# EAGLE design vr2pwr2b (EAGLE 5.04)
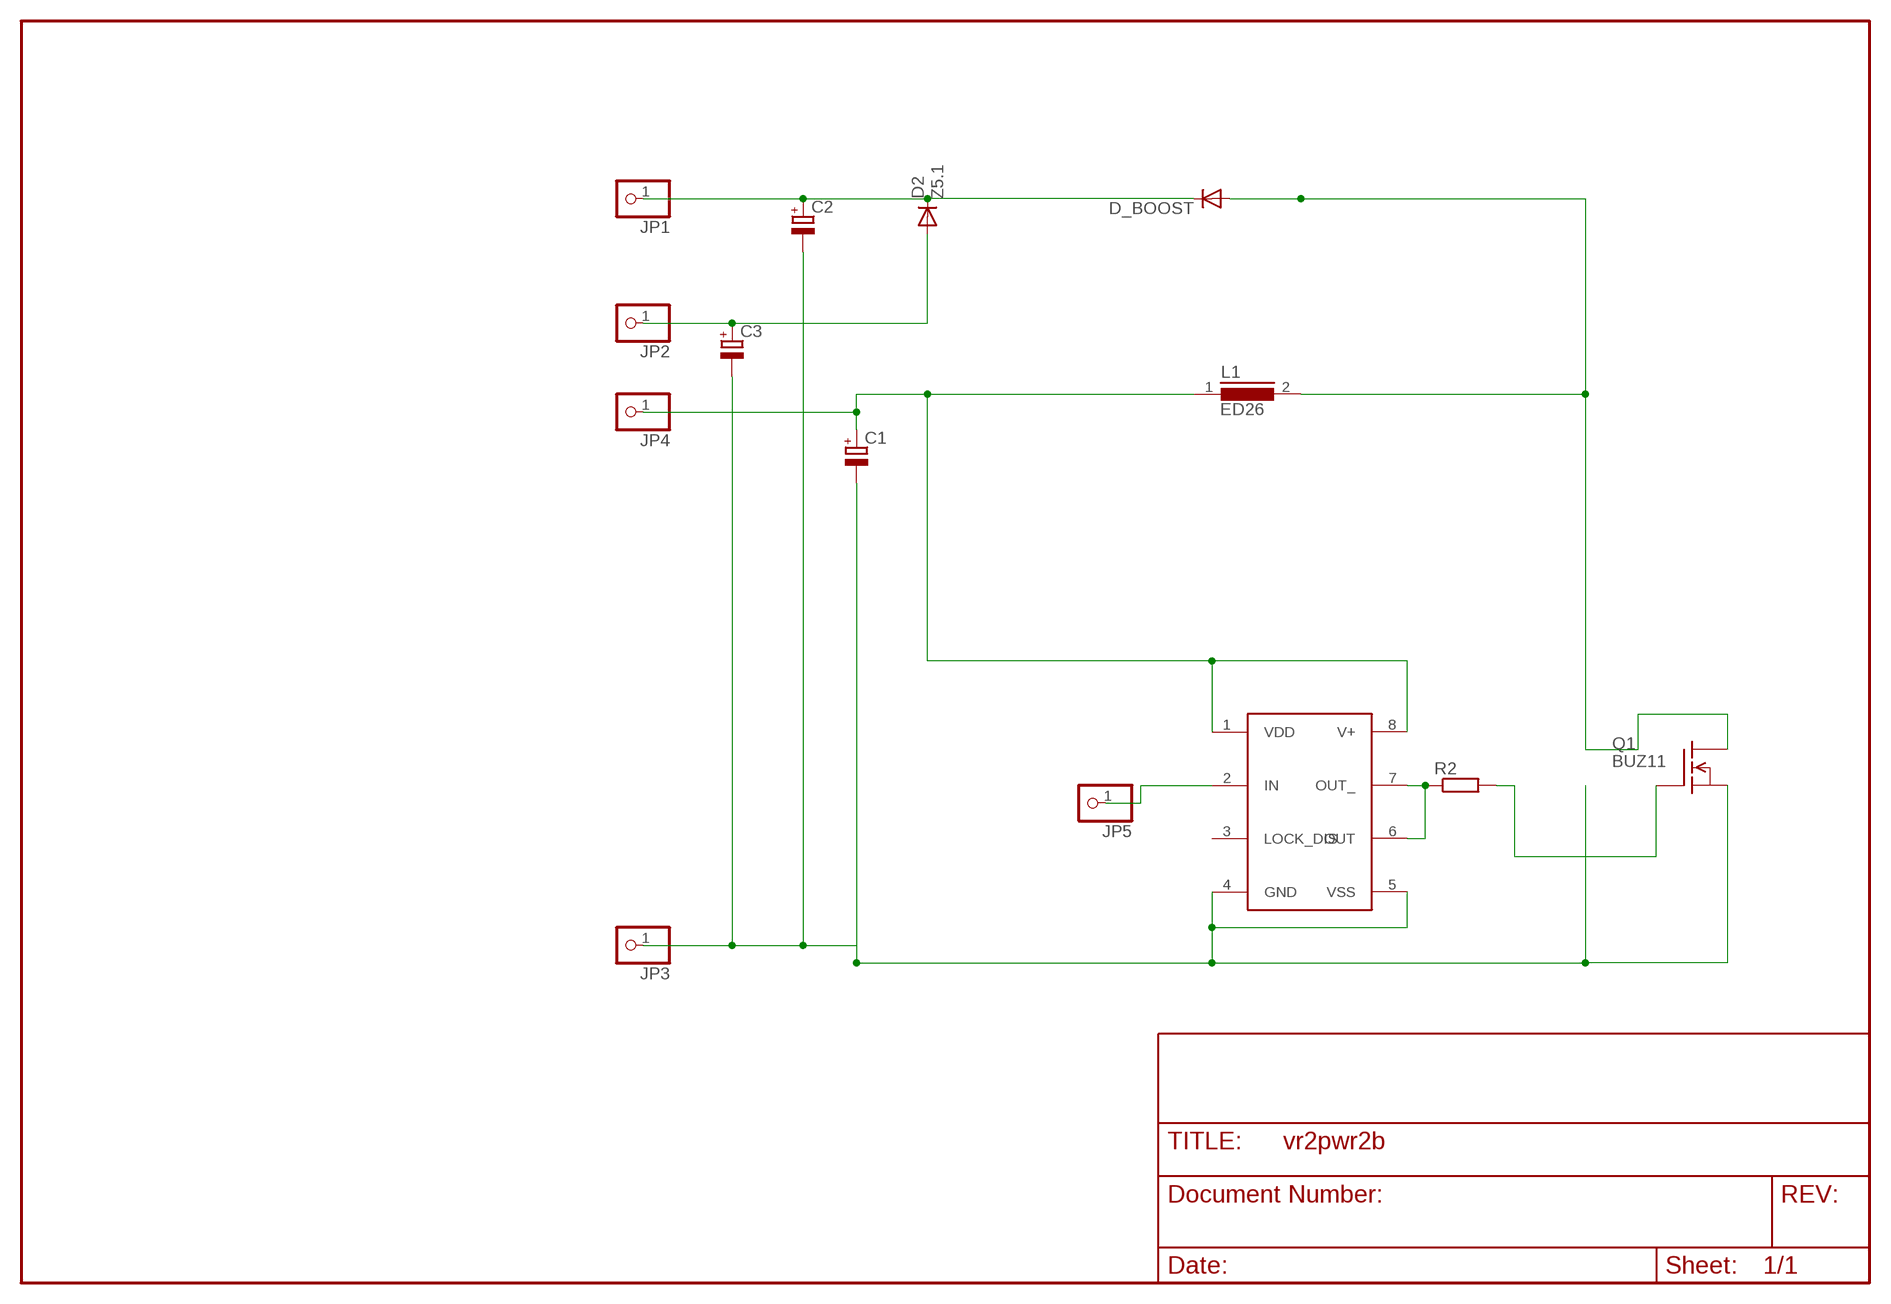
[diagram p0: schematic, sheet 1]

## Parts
C1  CPOL-EUE2.5-7  [E2,5-7]
C2  CPOL-EUE2.5-7  [E2,5-7]
C3  CPOL-EUE2-4  [E2-4]
D2  Z5.1  DIODE-D-2.5  [D-2.5]
D_BOOST  DIODE-D-10  [D-10]
IC1  TC4432X  [SO-08]
JP1  PINHD-1X1  [1X01]
JP2  PINHD-1X1  [1X01]
JP3  PINHD-1X1  [1X01]
JP4  PINHD-1X1  [1X01]
JP5  PINHD-1X1  [1X01]
L1  ED26  [ED26]
Q1  BUZ11  [TO220V]
R2  R-EU_R1206  [R1206]

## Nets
GND: C1.- C2.- C3.- IC1.4(GND) IC1.5(VSS) JP3.1 Q1.3(S)
HOTSPOT: D_BOOST.A L1.2 Q1.2(D)
LOAD: C2.+ D2.C D_BOOST.C JP1.1
N$1: IC1.2(IN) JP5.1
N$2: C1.+ IC1.1(VDD) IC1.8(V+) JP4.1 L1.1
N$3: IC1.6(OUT) IC1.7(OUT_) R2.1
N$4: C3.+ D2.A JP2.1
N$6: Q1.1(G) R2.2
Unconnected: IC1.3(LOCK_DIS)

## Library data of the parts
C1-C3 = rcl(2):CPOL-EU: POLARIZED CAPACITOR, European symbol
D2 D_BOOST = diode:DIODE-: DIODE
IC1 = microchip:TC4432
JP1-JP5 = pinhead:PINHD-1X1: PIN HEADER
L1 = inductors:ED26: INDUCTOR
Q1 = transistor-fet:BUZ11: N-Channel Enhancement MOSFET 50V; 30A; 0,040Ohm
R2 = rcl-2:R-EU_: RESISTOR, European symbol

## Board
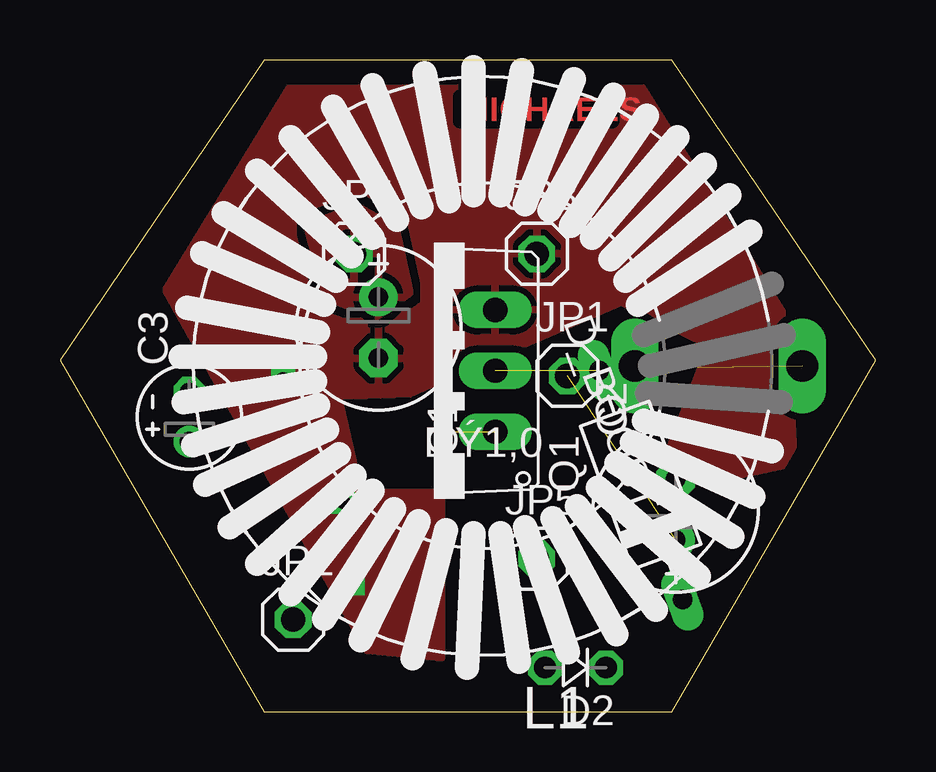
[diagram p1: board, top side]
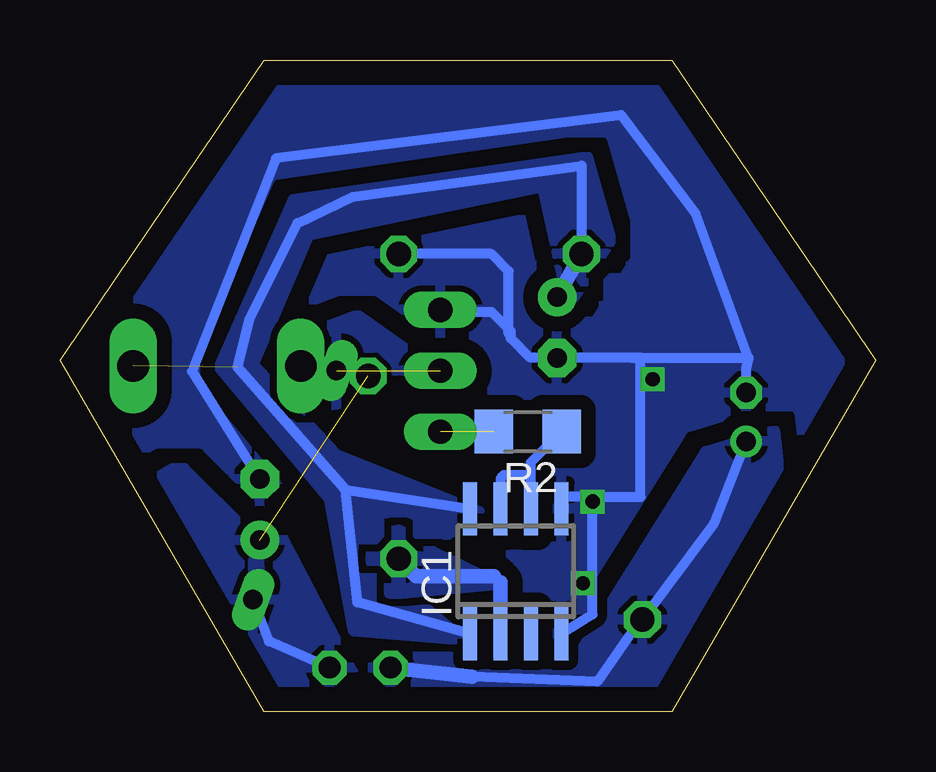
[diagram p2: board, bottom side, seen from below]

Size 34 x 27.15 mm. Coordinates in mm from the lower left corner, seen from the top.
Outline: 8.5,0 25.5,0 34,14.65 25.5,27.15 8.5,27.15 0,14.65 8.5,0
Copper layers (1*16): Top 0.035mm / dielectric 1.5mm / Bottom 0.035mm
Design rules "default": minimum track width 10mil, minimum drill 24mil, track to track 8mil, track to pad 8mil, pad to pad 8mil, via to via 8mil, smd to smd 8mil, copper to edge 40mil, drill to drill 8mil, minimum pad ring 10mil, minimum via ring 8mil, stop-mask expansion 4mil, vias tented up to drill 0mil, thermal gap 10mil

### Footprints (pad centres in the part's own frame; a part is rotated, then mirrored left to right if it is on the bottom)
E2,5-7 = drill 0.813 pad 1.6 round: + -1.27,0 | drill 0.813 pad 1.6 octagon: - 1.27,0
E2-4 = drill 0.813 pad 1.27 round: + -1.016,0 | drill 0.813 pad 1.27 octagon: - 1.016,0
D-2.5 = drill 0.9 octagon: A 1.27,0; C -1.27,0
D-10 = drill 0.813 long: A 5.08,0; C -5.08,0
SO-08 = smd 0.6 x 2.2: 1 -1.905,-2.6; 2 -0.635,-2.6; 3 0.635,-2.6; 4 1.905,-2.6; 5 1.905,2.6; 6 0.635,2.6; 7 -0.635,2.6; 8 -1.905,2.6
1X01 = drill 1.016 octagon: 1 0,0
ED26 = drill 1.321 long: 1 -13.335,0; 2 -6.35,0
TO220V = drill 1.016 long: 1 -2.54,-2.54; 2 0,-2.54; 3 2.54,-2.54
R1206 = smd 1.6 x 1.803: 1 -1.422,0; 2 1.422,0

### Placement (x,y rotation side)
C1  13.28,15.99 270 top
C2  25.67,8.41 90 top
C3  5.39,12.27 90 top
D2  21.49,1.83 180 top
D_BOOST  24.21,9.44 110 top
IC1  15,5.85 0 bottom
JP1  21.15,13.99 0 top
JP2  9.72,3.83 0 top
JP3  19.88,19.07 0 top
JP4  12.26,19.07 0 top
JP5  19.88,6.37 0 top
L1  17.61,14.41 180 top
Q1  15.6,14.2 90 top
R2  14.5,11.67 180 bottom

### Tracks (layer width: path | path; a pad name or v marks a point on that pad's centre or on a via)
GND  (via drill 0.6)
  Bottom 0.406: IC1.4 11.8,4.05 v11.8,8.75 11.8,8.95 | 11.8,8.95 12.99,8.95 IC1.5 | 11.8,8.95 9.8,8.95 9.8,14.75 10.2,14.75 | 10.2,14.75 13.28,14.75 | 13.28,14.75 C1.- | C2.- 28.5,14.18 25,23.05 10.6,24.85 7.5,20.75 5.3,14.75 | 10.2,14.75 5.3,14.75 | C3.- 5.4,14.29 5.3,14.75 | 13.28,14.75 14.4,14.75 15.2,15.55 15.2,15.65 | 15.2,15.65 15.2,15.85 16,16.65 17.81,16.65 | JP3.1 16.02,19.07 15.3,18.35 15.3,15.75 15.2,15.65
  other vias: 12.2,5.35 9.3,13.85
  pour Bottom (isolate 0.61, rank 3): 0.9,13.75 8,27.35 26.5,27.55 32.7,13.85 24.8,2.45 9.9,2.35
  pour Top (isolate 0.305, rank 3): 23.8,26.75 30.3,16.35 30.6,10.35 24.7,9.05 27.1,15.25 23.4,17.05 14.6,13.25 11.6,13.15 12.5,9.15 15.9,9.15 15.9,2.25 12.8,2.55 4.4,17.55 10.1,26.85
HOTSPOT  (1 unrouted)
  Bottom 0.406: D_BOOST.A L1.2
  pour Bottom: 18.3,14.25 21.6,16.55 24.8,15.35 23.8,12.55 20.1,13.25
LOAD  (1 unrouted)
  Bottom 0.406: D2.C 25.28,2.93 D_BOOST.C
  pour Bottom: 23.7,-1.55 21.3,0.75 24.8,7.45 26.1,7.45 28.8,10.15 29.3,10.15 31.7,8.75
N$1
  Bottom 0.406: 15.63,5.38 15.9,5.65
  Bottom 0.61: IC1.2 15.63,5.38 | 15.9,5.65 19.16,5.65 JP5.1
  pour Bottom (isolate 0.305): 18.4,6.55 20.1,7.65 21.2,6.65 20.2,4.95 15.9,5.35
N$2  (1 unrouted)
  Bottom 0.406: 22.1,9.25 IC1.8 | 22.1,9.25 21.6,4.55 IC1.1 | 22.1,9.25 26.6,14.35 26.1,16.35 24.1,20.35 21.8,21.45 12.26,22.75 JP4.1
  Bottom 0.61: JP4.1 C1.+
  pour Bottom (isolate 0.305, rank 2): 12.8,16.85 11,19.65 12,23.15 24.3,21.35 27.4,14.35 22.8,8.85 21.8,3.35 17.1,2.95 20.2,5.55 16.5,8.35 22.5,10.75 25.9,14.45 23.6,19.85 13.9,21.85
  pour Top (isolate 0.305, rank 2): 12.4,21.05 14,20.15 14.6,17.45 13.2,16.45 11.1,17.25 10.3,20.25
N$3
  Bottom 0.406: IC1.6 14.37,9.85 | 14.37,9.85 14.37,10.38 R2.1 | IC1.7 15.63,9.71 15.5,9.85 14.37,9.85
N$4
  Bottom 0.406: C3.+ 6.72,7.86 JP2.1 9.8,3.83 11.6,1.25 16.82,1.45
  Bottom 0.61: 16.82,1.45 D2.A
  pour Bottom (isolate 0.406, rank 2): 4.2,11.75 4,9.85 9.5,-0.05 21.5,-0.15 21.1,2.35 12.5,2.25 7.1,10.85
N$6  (1 unrouted)

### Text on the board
Top: MICHAELS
